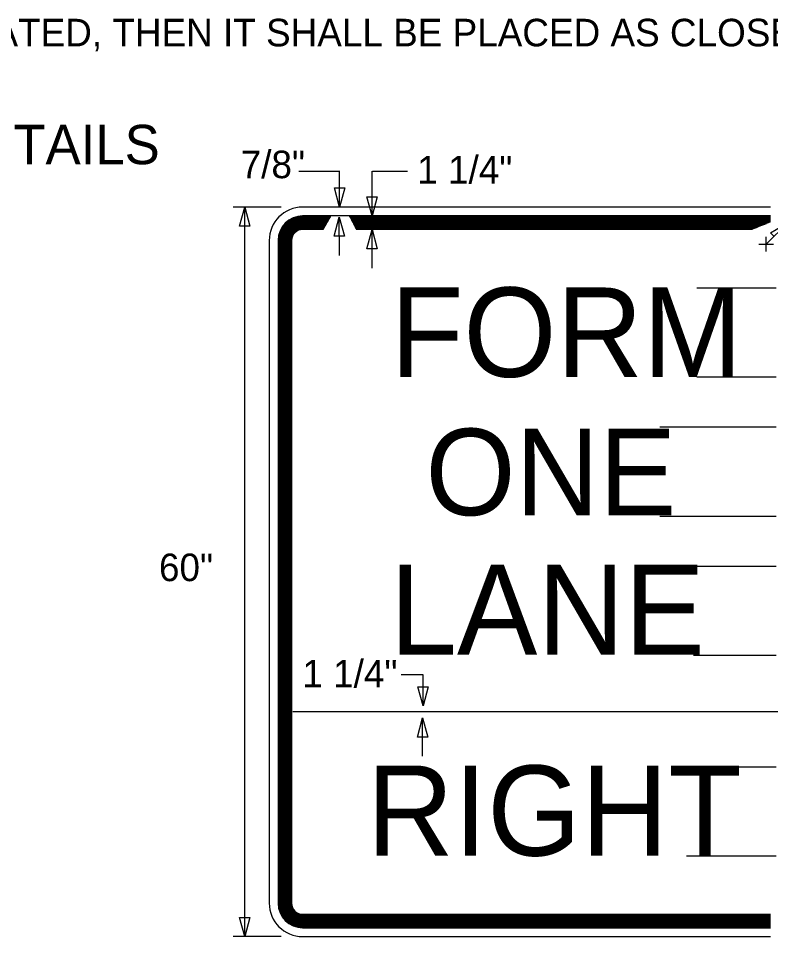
# Model space of a CAD drawing. Extents: x 15273 to 18137, y 1908 to 6555.
# Drawn here: x 17745.2 to 17974.2, y 2387.3 to 2667.1 of the extents above; entities that cross this region are included whole.
import ezdxf

# ---------------------------------------------------------------- set-up
doc = ezdxf.new("R2010")
doc.units = 0
for name, color, linetype in [('TYPICAL_EX', 7, 'Continuous'), ('TYPICAL_TEXT_DIMEN_EX', 7, 'Continuous'), ('TYPICAL_TEXT_DIMEN_PR', 7, 'Continuous')]:
    doc.layers.add(name, color=color, linetype=linetype)

msp = doc.modelspace()

# ---------------------------------------------------------------- linework, layer by layer
at = {"layer": 'TYPICAL_EX'}
for p, q in [((17974.24, 2609.62), (17831.73, 2609.62)), ((17840.43, 2606.91), (17831.73, 2606.91)), ((17840.36, 2606.79), (17831.73, 2606.79)), ((17840.3, 2606.68), (17831.73, 2606.68)), ((17840.23, 2606.57), (17831.73, 2606.57)), ((17840.17, 2606.46), (17831.73, 2606.46)), ((17840.1, 2606.35), (17831.73, 2606.35)), ((17840.04, 2606.23), (17831.73, 2606.23)), ((17839.97, 2606.12), (17831.73, 2606.12)), ((17839.91, 2606.01), (17831.73, 2606.01)), ((17839.85, 2605.9), (17831.73, 2605.9)), ((17839.78, 2605.79), (17831.73, 2605.79)), ((17839.72, 2605.67), (17831.73, 2605.67)), ((17839.65, 2605.56), (17831.73, 2605.56)), ((17839.59, 2605.45), (17831.73, 2605.45)), ((17839.52, 2605.34), (17831.73, 2605.34)), ((17839.46, 2605.23), (17831.73, 2605.23)), ((17839.39, 2605.11), (17831.73, 2605.11)), ((17839.33, 2605), (17831.73, 2605)), ((17839.26, 2604.89), (17831.73, 2604.89)), ((17844.36, 2606.91), (17840.35, 2606.91)), ((17974.24, 2606.91), (17844.36, 2606.91)), ((17974.24, 2606.79), (17845.88, 2606.79)), ((17974.24, 2606.68), (17846.02, 2606.68)), ((17974.24, 2606.57), (17846.08, 2606.57)), ((17974.24, 2606.46), (17846.14, 2606.46)), ((17974.24, 2606.35), (17846.2, 2606.35)), ((17974.24, 2606.23), (17846.26, 2606.23)), ((17974.24, 2606.12), (17846.31, 2606.12)), ((17974.24, 2606.01), (17846.37, 2606.01)), ((17974.24, 2605.9), (17846.43, 2605.9)), ((17974.24, 2605.79), (17846.49, 2605.79)), ((17974.24, 2605.67), (17846.55, 2605.67)), ((17974.24, 2605.56), (17846.6, 2605.56)), ((17974.24, 2605.45), (17846.66, 2605.45)), ((17974.24, 2605.34), (17846.72, 2605.34)), ((17974.24, 2605.23), (17846.78, 2605.23)), ((17974.24, 2605.11), (17846.84, 2605.11)), ((17974.11, 2605), (17846.89, 2605)), ((17973.83, 2604.89), (17846.95, 2604.89)), ((17839.2, 2604.78), (17831.73, 2604.78)), ((17839.14, 2604.67), (17831.73, 2604.67)), ((17839.07, 2604.55), (17831.73, 2604.55)), ((17839.01, 2604.44), (17831.73, 2604.44)), ((17838.94, 2604.33), (17831.73, 2604.33)), ((17838.88, 2604.22), (17831.73, 2604.22)), ((17838.81, 2604.11), (17831.73, 2604.11)), ((17838.75, 2603.99), (17831.73, 2603.99)), ((17838.68, 2603.88), (17831.73, 2603.88)), ((17838.62, 2603.77), (17831.73, 2603.77)), ((17838.55, 2603.66), (17831.73, 2603.66)), ((17838.49, 2603.54), (17831.73, 2603.54)), ((17838.42, 2603.43), (17831.73, 2603.43)), ((17838.36, 2603.32), (17831.73, 2603.32)), ((17838.3, 2603.21), (17831.73, 2603.21)), ((17838.23, 2603.1), (17831.73, 2603.1)), ((17838.17, 2602.98), (17831.73, 2602.98)), ((17838.1, 2602.87), (17831.73, 2602.87)), ((17838.06, 2602.8), (17831.73, 2602.8)), ((17973.55, 2604.78), (17847.01, 2604.78)), ((17973.27, 2604.67), (17847.07, 2604.67)), ((17972.99, 2604.55), (17847.12, 2604.55)), ((17972.71, 2604.44), (17847.18, 2604.44)), ((17972.43, 2604.33), (17847.24, 2604.33)), ((17972.15, 2604.22), (17847.3, 2604.22)), ((17971.87, 2604.11), (17847.36, 2604.11)), ((17971.58, 2603.99), (17847.42, 2603.99)), ((17971.3, 2603.88), (17847.47, 2603.88)), ((17971.02, 2603.77), (17847.53, 2603.77)), ((17970.74, 2603.66), (17847.59, 2603.66)), ((17970.46, 2603.54), (17847.65, 2603.54)), ((17970.18, 2603.43), (17847.71, 2603.43)), ((17969.9, 2603.32), (17847.76, 2603.32)), ((17969.62, 2603.21), (17847.82, 2603.21)), ((17969.34, 2603.1), (17847.88, 2603.1)), ((17969.06, 2602.98), (17847.94, 2602.98)), ((17968.78, 2602.87), (17847.99, 2602.87)), ((17968.59, 2602.8), (17848.03, 2602.8)), ((17821.55, 2599.44), (17821.55, 2451.35)), ((17824.27, 2599.44), (17824.27, 2451.35)), ((17824.38, 2599.44), (17824.38, 2451.35)), ((17824.49, 2599.44), (17824.49, 2451.35)), ((17824.6, 2599.44), (17824.6, 2451.35)), ((17824.71, 2599.44), (17824.71, 2451.22)), ((17824.83, 2599.44), (17824.83, 2451.35)), ((17824.94, 2599.44), (17824.94, 2451.35)), ((17825.05, 2599.44), (17825.05, 2451.33)), ((17825.16, 2599.44), (17825.16, 2451.36)), ((17825.27, 2599.44), (17825.27, 2451.31)), ((17825.39, 2599.44), (17825.39, 2451.35)), ((17825.5, 2599.44), (17825.5, 2451.35)), ((17825.61, 2599.44), (17825.61, 2451.39)), ((17825.72, 2599.44), (17825.72, 2451.35)), ((17825.83, 2599.44), (17825.83, 2451.35)), ((17825.95, 2599.44), (17825.95, 2451.35)), ((17826.06, 2599.44), (17826.06, 2451.35)), ((17826.17, 2599.44), (17826.17, 2451.35)), ((17826.28, 2599.44), (17826.28, 2451.34)), ((17826.4, 2599.44), (17826.4, 2451.35)), ((17826.51, 2599.44), (17826.51, 2451.37)), ((17826.62, 2599.44), (17826.62, 2451.35)), ((17826.73, 2599.44), (17826.73, 2451.35)), ((17826.84, 2599.44), (17826.84, 2451.34)), ((17826.96, 2599.44), (17826.96, 2451.37)), ((17827.07, 2599.44), (17827.07, 2451.35)), ((17827.18, 2599.44), (17827.18, 2451.35)), ((17827.29, 2599.44), (17827.29, 2470.06)), ((17827.4, 2599.44), (17827.4, 2470.06)), ((17827.51, 2599.44), (17827.51, 2470.06)), ((17827.63, 2599.44), (17827.63, 2451.35)), ((17827.74, 2599.44), (17827.74, 2451.34)), ((17827.85, 2599.44), (17827.85, 2451.35)), ((17827.96, 2599.44), (17827.96, 2451.34)), ((17828.08, 2599.44), (17828.08, 2451.35)), ((17828.19, 2599.44), (17828.19, 2451.37)), ((17828.3, 2599.44), (17828.3, 2451.36)), ((17828.38, 2599.44), (17828.38, 2451.37)), ((17827.29, 2470.13), (17827.29, 2397.51)), ((17827.4, 2470.06), (17827.4, 2397.51)), ((17827.51, 2470.06), (17827.51, 2397.51)), ((17828.79, 2455.92), (17977.54, 2455.92)), ((17821.55, 2451.35), (17821.55, 2397.51)), ((17824.27, 2451.35), (17824.27, 2397.51)), ((17824.38, 2451.35), (17824.38, 2397.51)), ((17824.49, 2451.35), (17824.49, 2397.51)), ((17824.6, 2451.35), (17824.6, 2397.51)), ((17824.71, 2451.35), (17824.71, 2397.51)), ((17824.83, 2451.35), (17824.83, 2397.51)), ((17824.94, 2451.35), (17824.94, 2397.51)), ((17825.05, 2451.35), (17825.05, 2396.83)), ((17825.16, 2451.35), (17825.16, 2397.51)), ((17825.27, 2451.35), (17825.27, 2397.51)), ((17825.39, 2451.35), (17825.39, 2397.51)), ((17825.5, 2451.35), (17825.5, 2397.51)), ((17825.61, 2451.4), (17825.61, 2397.51)), ((17825.72, 2451.35), (17825.72, 2397.51)), ((17825.83, 2451.35), (17825.83, 2397.51)), ((17825.95, 2451.35), (17825.95, 2397.51)), ((17826.06, 2451.35), (17826.06, 2397.51)), ((17826.17, 2451.35), (17826.17, 2397.51)), ((17826.28, 2451.35), (17826.28, 2397.51)), ((17826.4, 2451.35), (17826.4, 2397.51)), ((17826.51, 2451.35), (17826.51, 2397.51)), ((17826.62, 2451.35), (17826.62, 2397.51)), ((17826.73, 2451.35), (17826.73, 2397.51)), ((17826.84, 2451.35), (17826.84, 2397.51)), ((17826.96, 2451.35), (17826.96, 2397.51)), ((17827.07, 2451.35), (17827.07, 2397.51)), ((17827.18, 2451.35), (17827.18, 2397.51)), ((17827.63, 2451.35), (17827.63, 2397.51)), ((17827.74, 2451.35), (17827.74, 2397.51)), ((17827.85, 2451.35), (17827.85, 2397.51)), ((17827.96, 2451.34), (17827.96, 2397.51)), ((17828.08, 2451.35), (17828.08, 2397.51)), ((17828.19, 2451.35), (17828.19, 2397.51)), ((17828.3, 2451.35), (17828.3, 2397.51)), ((17828.38, 2451.35), (17828.38, 2397.51)), ((17831.73, 2394.15), (17974.24, 2394.15)), ((17831.73, 2394.08), (17974.24, 2394.08)), ((17831.73, 2393.96), (17974.24, 2393.96)), ((17831.73, 2393.85), (17974.24, 2393.85)), ((17831.73, 2393.74), (17974.24, 2393.74)), ((17831.73, 2393.63), (17974.24, 2393.63)), ((17831.73, 2393.52), (17974.24, 2393.52)), ((17831.73, 2393.4), (17974.24, 2393.4)), ((17831.73, 2393.29), (17974.24, 2393.29)), ((17831.73, 2393.18), (17974.24, 2393.18)), ((17831.73, 2393.07), (17974.24, 2393.07)), ((17831.73, 2392.96), (17974.24, 2392.96)), ((17831.73, 2392.84), (17974.24, 2392.84)), ((17831.73, 2392.73), (17974.24, 2392.73)), ((17831.73, 2392.62), (17974.24, 2392.62)), ((17831.73, 2392.51), (17974.24, 2392.51)), ((17831.73, 2392.4), (17974.24, 2392.4)), ((17831.73, 2392.28), (17974.24, 2392.28)), ((17831.73, 2392.17), (17974.24, 2392.17)), ((17831.73, 2392.06), (17974.24, 2392.06)), ((17831.73, 2391.95), (17974.24, 2391.95)), ((17831.73, 2391.84), (17974.24, 2391.84)), ((17831.73, 2391.72), (17974.24, 2391.72)), ((17831.73, 2391.61), (17974.24, 2391.61)), ((17831.73, 2391.5), (17974.24, 2391.5)), ((17831.73, 2391.39), (17974.24, 2391.39)), ((17831.73, 2391.27), (17974.24, 2391.27)), ((17831.73, 2391.16), (17974.24, 2391.16)), ((17831.73, 2391.05), (17974.24, 2391.05)), ((17831.73, 2390.94), (17974.24, 2390.94)), ((17831.73, 2390.83), (17974.24, 2390.83)), ((17831.73, 2390.71), (17974.24, 2390.71)), ((17831.73, 2390.6), (17974.24, 2390.6)), ((17831.73, 2390.49), (17974.24, 2390.49)), ((17831.73, 2390.38), (17974.24, 2390.38)), ((17831.73, 2390.27), (17974.24, 2390.27)), ((17831.73, 2390.15), (17974.24, 2390.15)), ((17831.73, 2390.04), (17974.24, 2390.04)), ((17831.73, 2387.33), (17974.24, 2387.33))]:
    msp.add_line(p, q, dxfattribs=at)
for centre, radius, start, end in [((17831.73, 2599.44), 10.18, 90, 180), ((17831.73, 2599.44), 7.46, 90, 180), ((17831.73, 2599.44), 7.35, 90, 180), ((17831.73, 2599.44), 7.24, 90, 180), ((17831.73, 2599.44), 7.13, 90, 180), ((17831.73, 2599.44), 7.02, 90, 180), ((17831.73, 2599.44), 6.9, 90, 180), ((17831.73, 2599.44), 6.79, 90, 180), ((17831.73, 2599.44), 6.68, 90, 180), ((17831.73, 2599.44), 6.57, 90, 180), ((17831.73, 2599.44), 6.46, 90, 180), ((17831.73, 2599.44), 6.34, 90, 180), ((17831.73, 2599.44), 6.23, 90, 180), ((17831.73, 2599.44), 6.12, 90, 180), ((17831.73, 2599.44), 6.01, 90, 180), ((17831.73, 2599.44), 5.9, 90, 180), ((17831.73, 2599.44), 5.78, 90, 180), ((17831.73, 2599.44), 5.67, 90, 180), ((17831.73, 2599.44), 5.56, 90, 180), ((17831.73, 2599.44), 5.45, 90, 180), ((17831.73, 2599.44), 5.34, 90, 180), ((17831.73, 2599.44), 5.22, 90, 180), ((17831.73, 2599.44), 5.11, 90, 180), ((17831.73, 2599.44), 5, 90, 180), ((17831.73, 2599.44), 4.89, 90, 180), ((17831.73, 2599.44), 4.78, 90, 180), ((17831.73, 2599.44), 4.66, 90, 180), ((17831.73, 2599.44), 4.55, 90, 180), ((17831.73, 2599.44), 4.44, 90, 180), ((17831.73, 2599.44), 4.33, 90, 180), ((17831.73, 2599.44), 4.21, 90, 180), ((17831.73, 2599.44), 4.1, 90, 180), ((17831.73, 2599.44), 3.99, 90, 180), ((17831.73, 2599.44), 3.88, 90, 180), ((17831.73, 2599.44), 3.77, 90, 180), ((17831.73, 2599.44), 3.65, 90, 180), ((17831.73, 2599.44), 3.54, 90, 180), ((17831.73, 2599.44), 3.43, 90, 180), ((17831.73, 2599.44), 3.36, 90, 180), ((17831.73, 2397.51), 10.18, 180, 270), ((17831.73, 2397.51), 7.46, 180, 270), ((17831.73, 2397.51), 7.35, 180, 270), ((17831.73, 2397.51), 7.24, 180, 270), ((17831.73, 2397.51), 7.13, 180, 270), ((17831.73, 2397.51), 7.02, 180, 270), ((17831.73, 2397.51), 6.9, 180, 270), ((17831.73, 2397.51), 6.79, 180, 270), ((17831.73, 2397.51), 6.68, 180, 270), ((17831.73, 2397.51), 6.57, 180, 270), ((17831.73, 2397.51), 6.46, 180, 270), ((17831.73, 2397.51), 6.34, 180, 270), ((17831.73, 2397.51), 6.23, 180, 270), ((17831.73, 2397.51), 6.12, 180, 270), ((17831.73, 2397.51), 6.01, 180, 270), ((17831.73, 2397.51), 5.9, 180, 270), ((17831.73, 2397.51), 5.78, 180, 270), ((17831.73, 2397.51), 5.67, 180, 270), ((17831.73, 2397.51), 5.56, 180, 270), ((17831.73, 2397.51), 5.45, 180, 270), ((17831.73, 2397.51), 5.34, 180, 270), ((17831.73, 2397.51), 5.22, 180, 270), ((17831.73, 2397.51), 5.11, 180, 270), ((17831.73, 2397.51), 5, 180, 270), ((17831.73, 2397.51), 4.89, 180, 270), ((17831.73, 2397.51), 4.78, 180, 270), ((17831.73, 2397.51), 4.66, 180, 270), ((17831.73, 2397.51), 4.55, 180, 270), ((17831.73, 2397.51), 4.44, 180, 270), ((17831.73, 2397.51), 4.33, 180, 270), ((17831.73, 2397.51), 4.21, 180, 270), ((17831.73, 2397.51), 4.1, 180, 270), ((17831.73, 2397.51), 3.99, 180, 270), ((17831.73, 2397.51), 3.88, 180, 270), ((17831.73, 2397.51), 3.77, 180, 270), ((17831.73, 2397.51), 3.65, 180, 270), ((17831.73, 2397.51), 3.54, 180, 270), ((17831.73, 2397.51), 3.43, 180, 270), ((17831.73, 2397.51), 3.36, 180, 270)]:
    msp.add_arc(centre, radius, start, end, dxfattribs=at)
at = {"layer": 'TYPICAL_TEXT_DIMEN_PR'}
for p, q in [((17830.54, 2620.54), (17842.99, 2620.52)), ((17842.99, 2609.62), (17842.98, 2620.63)), ((17852.88, 2606.91), (17852.88, 2620.54)), ((17853.05, 2620.61), (17863.62, 2620.61)), ((17842.99, 2609.62), (17841.41, 2615.48)), ((17841.41, 2615.48), (17842.98, 2615.48)), ((17842.98, 2615.48), (17844.56, 2615.48)), ((17844.56, 2615.48), (17842.99, 2609.62)), ((17852.88, 2606.91), (17851.31, 2612.77)), ((17851.31, 2612.77), (17852.88, 2612.77)), ((17852.88, 2612.77), (17854.45, 2612.77)), ((17854.45, 2612.77), (17852.88, 2606.91)), ((17825.18, 2609.62), (17810.57, 2609.62)), ((17812.54, 2603.76), (17814.11, 2609.62)), ((17814.11, 2451.35), (17814.11, 2609.62)), ((17814.11, 2609.62), (17815.68, 2603.76)), ((17841.32, 2600.71), (17842.88, 2606.57)), ((17842.91, 2594.86), (17842.88, 2606.57)), ((17842.88, 2606.57), (17844.47, 2600.72)), ((17852.88, 2607.17), (17852.88, 2607.17)), ((17852.88, 2607.17), (17852.88, 2607.17)), ((17814.11, 2603.76), (17812.54, 2603.76)), ((17815.68, 2603.76), (17814.11, 2603.76)), ((17851.31, 2596.93), (17852.88, 2602.8)), ((17852.88, 2591.02), (17852.88, 2602.8)), ((17852.88, 2602.8), (17854.45, 2596.93)), ((17972.91, 2598.28), (17979.44, 2604.81)), ((17974.18, 2601.77), (17979.43, 2604.81)), ((17842.9, 2600.71), (17841.32, 2600.71)), ((17844.47, 2600.72), (17842.9, 2600.71)), ((17972.91, 2596.04), (17972.91, 2600.52)), ((17975.29, 2600.66), (17974.18, 2601.77)), ((17852.88, 2596.93), (17851.31, 2596.93)), ((17854.45, 2596.93), (17852.88, 2596.93)), ((17970.67, 2598.28), (17972.91, 2598.28)), ((17972.91, 2598.28), (17975.15, 2598.28)), ((17951.77, 2585.02), (17975.94, 2585.02)), ((17951.77, 2557.88), (17975.94, 2557.88)), ((17940.51, 2542.61), (17975.94, 2542.61)), ((17940.51, 2515.46), (17975.94, 2515.46)), ((17950.76, 2500.19), (17975.94, 2500.19)), ((17950.76, 2473.05), (17975.94, 2473.05)), ((17868.4, 2467.09), (17861.74, 2467.09)), ((17868.4, 2457.63), (17868.4, 2467.09)), ((17868.4, 2457.63), (17866.83, 2463.49)), ((17866.83, 2463.49), (17868.4, 2463.49)), ((17868.4, 2463.49), (17869.98, 2463.49)), ((17869.98, 2463.49), (17868.4, 2457.63)), ((17866.67, 2448.1), (17868.24, 2453.96)), ((17868.24, 2442.31), (17868.24, 2453.96)), ((17868.24, 2453.96), (17869.81, 2448.1)), ((17814.11, 2387.33), (17814.11, 2451.35)), ((17868.24, 2448.1), (17866.67, 2448.1)), ((17869.81, 2448.1), (17868.24, 2448.1)), ((17956.07, 2439.07), (17975.94, 2439.07)), ((17948.66, 2411.93), (17975.94, 2411.93)), ((17814.11, 2387.33), (17812.54, 2393.19)), ((17812.54, 2393.19), (17814.11, 2393.19)), ((17814.11, 2393.19), (17815.68, 2393.19)), ((17815.68, 2393.19), (17814.11, 2387.33)), ((17825.18, 2387.33), (17810.57, 2387.33))]:
    msp.add_line(p, q, dxfattribs=at)

# ---------------------------------------------------------------- texts
at = {"layer": 'TYPICAL_TEXT_DIMEN_EX'}
for s, height, p in [('FORM', 27.241, (17858.45, 2557.88)), ('ONE', 26.355, (17869.14, 2515.73)), ('LANE', 27.463, (17858.3, 2473.22)), ('RIGHT', 27.463, (17851.23, 2412))]:
    msp.add_text(s, height=height, dxfattribs=at).set_placement(p)
at = {"layer": 'TYPICAL_TEXT_DIMEN_PR'}
for s, height, p in [('LIMITATIONS RESTRICT ITS PLACEMENT AS INDICATED, THEN IT SHALL BE PLACED AS CLOSE TO THE BEGINNING', 8.4, (17463.6, 2658.59)), ('SIGN DETAILS', 12, (17677.65, 2622.68)), ('7/8"', 8.4, (17812.86, 2618.42)), ('1 1/4"', 8.4, (17866.63, 2616.8)), ('60"', 8.4, (17787.98, 2495.64)), ('1 1/4"', 8.4, (17831.64, 2463.25))]:
    msp.add_text(s, height=height, dxfattribs=at).set_placement(p)

doc.saveas('drawing.dxf')
